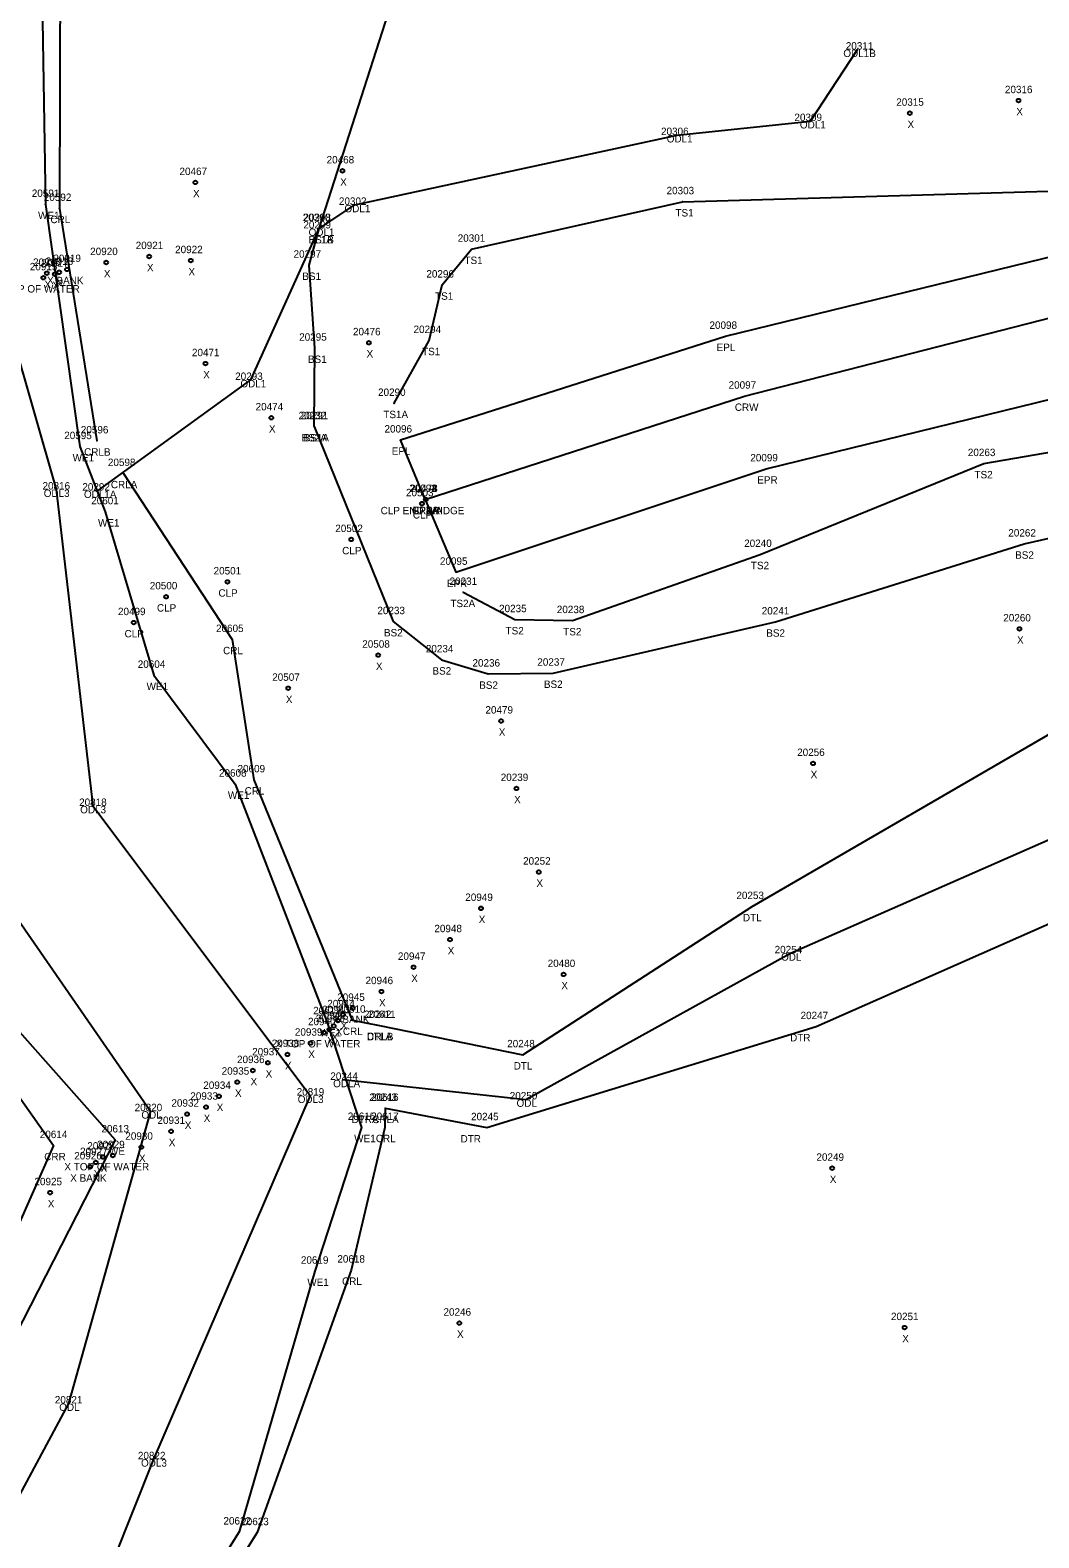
# Model space of a CAD drawing. Extents: x 1965722 to 1969964, y 1117078 to 1118461.
# Drawn here: x 1967825.7 to 1967961.8, y 1117755.3 to 1117958.8 of the extents above; entities that cross this region are included whole.
import ezdxf

# ---------------------------------------------------------------- set-up
doc = ezdxf.new("R2010")
doc.units = 0
for name, color, linetype in [('RD_DTM_BkLn1', 7, 'Continuous'), ('RD_DTM_BkLn2', 7, 'Continuous'), ('RD_EX_H2O', 7, 'Continuous'), ('RD_EX_H2O_txCode', 7, 'Continuous'), ('RD_EX_Road', 7, 'Continuous'), ('RD_EX_Road_txCode', 7, 'Continuous'), ('RD_SMD_Locator', 7, 'Continuous'), ('RD_SMD_Misc', 7, 'Continuous')]:
    doc.layers.add(name, color=color, linetype=linetype)

msp = doc.modelspace()

# ---------------------------------------------------------------- linework, layer by layer
at = {"layer": 'RD_DTM_BkLn1'}
for points in [[(1967864.65, 1117932.01), (1967874.44, 1117962.38), (1967900.7, 1118004.22), (1967938.17, 1118014.53)], [(1967878.98, 1117895.46), (1967922.07, 1117909.4), (1967968.89, 1117921.38), (1968013.49, 1117926.44), (1968059.29, 1117929.05), (1968105.63, 1117929.86), (1968159.12, 1117928.97), (1968212.65, 1117927.25), (1968318.5, 1117923.95), (1968422.42, 1117919.39), (1968529.36, 1117916.3)]]:
    msp.add_lwpolyline(points, dxfattribs=at)
at = {"layer": 'RD_DTM_BkLn2'}
for points in [[(1967874.77, 1117908.42), (1967879.51, 1117916.91), (1967881.27, 1117924.39), (1967885.24, 1117929.22), (1967913.7, 1117935.63), (1967966.11, 1117937.12), (1968012.39, 1117940.75), (1968059.42, 1117941.87), (1968105.44, 1117943.27), (1968158.32, 1117942.95), (1968212.48, 1117942.1), (1968371.25, 1117933.41), (1968422.85, 1117933.68), (1968531.49, 1117931.42)], [(1967864, 1117905.28), (1967864.09, 1117915.87), (1967863.33, 1117927.07), (1967864.65, 1117932.01)], [(1967884.1, 1117882.92), (1967891.06, 1117879.24), (1967898.84, 1117879.11), (1967924.17, 1117888.04), (1967954.33, 1117900.3), (1967970.81, 1117903.15), (1968012.93, 1117910.83), (1968059.62, 1117915.05), (1968105.25, 1117916.2), (1968157.57, 1117912.09), (1968210.74, 1117910.77), (1968320.32, 1117907.54), (1968423.18, 1117904.83), (1968528.99, 1117899.6)], [(1967864, 1117905.28), (1967874.64, 1117878.97), (1967881.18, 1117873.82), (1967887.49, 1117871.9), (1967896.22, 1117872.02), (1967926.22, 1117878.93), (1967959.79, 1117889.45), (1967973.08, 1117892.46), (1968014.67, 1117899.65), (1968058.49, 1117903.84)]]:
    msp.add_lwpolyline(points, dxfattribs=at)
at = {"layer": 'RD_EX_H2O'}
for points in [[(1967852.4, 1118390.04), (1967912.21, 1118383.64), (1967925.08, 1118336.82), (1967944.14, 1118294.4), (1967946.67, 1118243.15), (1967961.58, 1118191.28), (1967922.84, 1118148.62), (1967880.18, 1118117.11), (1967858.72, 1118073.64), (1967843.96, 1118030.69), (1967829.77, 1117984.65), (1967829.63, 1117934.73), (1967834.65, 1117903.36)], [(1967849.83, 1118135.18), (1967825.91, 1118086.77), (1967802.99, 1118041.98), (1967795.15, 1117992.28), (1967793.27, 1117935.35), (1967800.64, 1117889.8), (1967800.4, 1117872.52), (1967800.8, 1117854.99), (1967811.67, 1117837.73), (1967837.15, 1117809.04), (1967808.01, 1117752.12), (1967788.48, 1117706.78), (1967783.36, 1117689.17), (1967764.63, 1117648.93), (1967738.42, 1117613.44), (1967731.11, 1117607.31), (1967718.77, 1117573.47), (1967736.01, 1117517.29), (1967781.71, 1117484.69), (1967799.34, 1117478.73), (1967814.43, 1117469.18)], [(1967879.07, 1118118.61), (1967857.7, 1118074.04), (1967841.84, 1118031.93), (1967826.93, 1117984.9), (1967827.73, 1117935.27), (1967832.39, 1117902.59), (1967835.81, 1117893.8), (1967842.37, 1117871.73), (1967853.33, 1117857.05), (1967865.72, 1117824.99), (1967870.38, 1117810.73), (1967864.06, 1117791.33), (1967853.89, 1117756.14), (1967832.83, 1117722.61), (1967813.26, 1117679.41), (1967797.31, 1117630.26), (1967771.82, 1117595.7), (1967769.03, 1117583.97), (1967753.91, 1117565.22), (1967760.74, 1117542.39), (1967793.79, 1117511.28), (1967804.07, 1117502.92), (1967828.12, 1117499.18)], [(1967837.87, 1118086.59), (1967816.35, 1118042.52), (1967807.65, 1118000.54), (1967802.25, 1117964.95), (1967802.7, 1117929.05), (1967808.24, 1117891.66), (1967818.1, 1117847.27), (1967841.92, 1117812.91), (1967830.83, 1117773.47), (1967807.55, 1117730.13), (1967792.1, 1117688.21), (1967759.2, 1117626.42), (1967746.8, 1117597.58), (1967728.31, 1117575.82), (1967748.97, 1117519.79), (1967787.59, 1117491.86), (1967802.7, 1117484.72), (1967813.63, 1117479.24)], [(1967846.86, 1118079.71), (1967831.29, 1118034.88), (1967818.84, 1117997.76), (1967815.72, 1117964.67), (1967820.18, 1117928.06), (1967829.19, 1117896.79), (1967834.11, 1117854.1), (1967863.47, 1117815.02), (1967842.32, 1117765.95), (1967826.02, 1117725.1), (1967807.77, 1117682.35), (1967775.42, 1117611.81), (1967754.74, 1117587.12), (1967745.94, 1117565.65), (1967761.23, 1117525.28), (1967787.1, 1117502.15), (1967805.18, 1117494.11), (1967821.41, 1117490.36)], [(1967834.83, 1117896.65), (1967855.45, 1117911.58), (1967864.65, 1117932.01), (1967869.49, 1117935.2), (1967912.97, 1117944.62), (1967930.94, 1117946.51), (1967937.28, 1117956.15)], [(1967872.82, 1117824.49), (1967892.16, 1117820.53), (1967923.08, 1117840.53), (1967966.02, 1117865.44), (1967979.17, 1117870.44), (1968016.32, 1117890.41), (1968058.49, 1117903.84)], [(1967838.28, 1117898.96), (1967852.93, 1117876.56), (1967855.83, 1117857.63), (1967869.1, 1117825.19), (1967872.82, 1117824.49)], [(1967868.28, 1117817.14), (1967892.54, 1117814.5), (1967928.24, 1117834.22), (1967973.92, 1117854.29), (1967982.67, 1117861.15), (1968021.78, 1117883.3), (1968056.97, 1117897.44), (1968105.42, 1117898.77), (1968155.9, 1117899.84), (1968209.66, 1117898.76), (1968320.81, 1117895.57), (1968371.06, 1117895.25)], [(1967873.55, 1117813.3), (1967887.27, 1117810.69), (1967931.74, 1117824.33), (1967977.85, 1117844.69), (1967988.67, 1117850.69), (1968023.3, 1117871.08), (1968058.02, 1117883.74)], [(1967794.3, 1117875.45), (1967796.63, 1117853.43), (1967809.67, 1117835.4), (1967828.83, 1117808.28), (1967805.08, 1117754.56), (1967786.33, 1117708.04), (1967780.19, 1117689.35), (1967762.68, 1117651.19), (1967736.39, 1117616.3), (1967727.33, 1117611.21), (1967715.04, 1117573.35), (1967731.01, 1117514.73), (1967775.86, 1117468.11), (1967793.29, 1117458.88), (1967816.39, 1117454.18)], [(1967873.55, 1117813.3), (1967873.54, 1117810.73), (1967868.98, 1117791.48), (1967856.29, 1117756.05), (1967834.78, 1117721.72), (1967815.36, 1117678.52), (1967799.96, 1117628.39), (1967778.25, 1117587.63), (1967771.33, 1117582.11), (1967756.46, 1117564.6), (1967764.36, 1117543.85), (1967795.97, 1117517.33), (1967805.92, 1117513.21), (1967828.95, 1117503.56)]]:
    msp.add_lwpolyline(points, dxfattribs=at)
at = {"layer": 'RD_EX_Road'}
for points in [[(1967878.98, 1117895.46), (1967875.66, 1117903.48), (1967919.49, 1117917.47), (1967966.4, 1117928.95), (1968012.66, 1117935.42), (1968058.94, 1117938.37), (1968105.99, 1117939.39), (1968158.7, 1117938.56), (1968212.05, 1117937.21), (1968318.79, 1117933.28), (1968422.76, 1117929.93), (1968530.54, 1117925.7)], [(1967878.98, 1117895.46), (1967883.11, 1117885.63), (1967924.99, 1117899.59), (1967970.68, 1117910.78), (1968014.42, 1117916.56), (1968059.13, 1117919.49), (1968105.39, 1117920.31), (1968159.16, 1117919.37), (1968212.5, 1117917.97), (1968317.55, 1117914.44), (1968421.52, 1117910.75), (1968527.82, 1117906.41)]]:
    msp.add_lwpolyline(points, dxfattribs=at)
at = {"layer": 'RD_SMD_Locator'}
for centre, radius in [((1967937.28, 1117956.15), 0.001), ((1967959.04, 1117949.27), 0.25), ((1967944.36, 1117947.57), 0.25), ((1967930.94, 1117946.51), 0.001), ((1967912.97, 1117944.62), 0.001), ((1967867.81, 1117939.79), 0.25), ((1967847.96, 1117938.22), 0.25), ((1967827.73, 1117935.27), 0.001), ((1967913.7, 1117935.63), 0.001), ((1967829.63, 1117934.73), 0.001), ((1967869.49, 1117935.2), 0.001), ((1967864.65, 1117932.01), 0.001), ((1967864.65, 1117932.01), 0.001), ((1967864.65, 1117932.01), 0.001), ((1967885.24, 1117929.22), 0.001), ((1967835.93, 1117927.42), 0.25), ((1967841.74, 1117928.23), 0.25), ((1967847.35, 1117927.68), 0.25), ((1967827.45, 1117925.37), 0.25), ((1967827.92, 1117925.97), 0.25), ((1967829, 1117925.84), 0.25), ((1967829.59, 1117926.1), 0.25), ((1967830.64, 1117926.49), 0.25), ((1967863.33, 1117927.07), 0.001), ((1967881.27, 1117924.39), 0.001), ((1967879.51, 1117916.91), 0.001), ((1967919.49, 1117917.47), 0.001), ((1967864.09, 1117915.87), 0.001), ((1967871.37, 1117916.6), 0.25), ((1967849.33, 1117913.78), 0.25), ((1967855.45, 1117911.58), 0.001), ((1967922.07, 1117909.4), 0.001), ((1967874.77, 1117908.42), 0.001), ((1967858.21, 1117906.47), 0.25), ((1967864, 1117905.28), 0.001), ((1967864, 1117905.28), 0.001), ((1967834.65, 1117903.36), 0.001), ((1967875.66, 1117903.48), 0.001), ((1967832.39, 1117902.59), 0.001), ((1967838.28, 1117898.96), 0.001), ((1967924.99, 1117899.59), 0.001), ((1967954.33, 1117900.3), 0.001), ((1967829.19, 1117896.79), 0.001), ((1967834.83, 1117896.65), 0.001), ((1967878.54, 1117894.88), 0.25), ((1967879.05, 1117895.45), 0.25), ((1967878.98, 1117895.46), 0.001), ((1967878.98, 1117895.46), 0.001), ((1967878.98, 1117895.46), 0.001), ((1967835.81, 1117893.8), 0.001), ((1967869, 1117890.05), 0.25), ((1967959.79, 1117889.45), 0.001), ((1967924.17, 1117888.04), 0.001), ((1967852.29, 1117884.33), 0.25), ((1967883.11, 1117885.63), 0.001), ((1967844.01, 1117882.32), 0.25), ((1967884.1, 1117882.92), 0.001), ((1967839.64, 1117878.84), 0.25), ((1967874.64, 1117878.97), 0.001), ((1967891.06, 1117879.24), 0.001), ((1967898.84, 1117879.11), 0.001), ((1967926.22, 1117878.93), 0.001), ((1967852.93, 1117876.56), 0.001), ((1967959.15, 1117877.99), 0.25), ((1967872.64, 1117874.45), 0.25), ((1967881.18, 1117873.82), 0.001), ((1967842.37, 1117871.73), 0.001), ((1967860.49, 1117869.98), 0.25), ((1967887.49, 1117871.9), 0.001), ((1967896.22, 1117872.02), 0.001), ((1967889.22, 1117865.56), 0.25), ((1967931.3, 1117859.84), 0.25), ((1967853.33, 1117857.05), 0.001), ((1967855.83, 1117857.63), 0.001), ((1967891.28, 1117856.46), 0.25), ((1967834.11, 1117854.1), 0.001), ((1967894.3, 1117845.18), 0.25), ((1967886.5, 1117840.28), 0.25), ((1967923.08, 1117840.53), 0.001), ((1967882.32, 1117836.06), 0.25), ((1967928.24, 1117834.22), 0.001), ((1967877.41, 1117832.33), 0.25), ((1967897.65, 1117831.36), 0.25), ((1967873.06, 1117829.05), 0.25), ((1967867.2, 1117825.13), 0.25), ((1967867.88, 1117825.93), 0.25), ((1967869.21, 1117826.8), 0.25), ((1967865.32, 1117823.51), 0.25), ((1967865.72, 1117824.99), 0.001), ((1967866.04, 1117823.93), 0.25), ((1967866.64, 1117824.4), 0.25), ((1967869.1, 1117825.19), 0.001), ((1967872.82, 1117824.49), 0.001), ((1967872.82, 1117824.49), 0.001), ((1967931.74, 1117824.33), 0.001), ((1967863.5, 1117822.1), 0.25), ((1967857.75, 1117819.44), 0.25), ((1967860.38, 1117820.57), 0.25), ((1967892.16, 1117820.53), 0.001), ((1967855.73, 1117818.4), 0.25), ((1967853.62, 1117816.84), 0.25), ((1967868.28, 1117817.14), 0.001), ((1967849.4, 1117813.46), 0.25), ((1967851.15, 1117814.92), 0.25), ((1967863.47, 1117815.02), 0.001), ((1967873.55, 1117813.3), 0.001), ((1967873.55, 1117813.3), 0.001), ((1967892.54, 1117814.5), 0.001), ((1967841.92, 1117812.91), 0.001), ((1967846.84, 1117812.52), 0.25), ((1967844.69, 1117810.19), 0.25), ((1967870.38, 1117810.73), 0.001), ((1967873.54, 1117810.73), 0.001), ((1967887.27, 1117810.69), 0.001), ((1967828.83, 1117808.28), 0.001), ((1967836.83, 1117806.92), 0.25), ((1967837.15, 1117809.04), 0.001), ((1967840.67, 1117808.06), 0.25), ((1967833.76, 1117805.4), 0.25), ((1967834.53, 1117805.99), 0.25), ((1967835.5, 1117806.73), 0.25), ((1967933.88, 1117805.22), 0.25), ((1967828.37, 1117801.92), 0.25), ((1967864.06, 1117791.33), 0.001), ((1967868.98, 1117791.48), 0.001), ((1967883.58, 1117784.32), 0.25), ((1967943.66, 1117783.72), 0.25), ((1967830.83, 1117773.47), 0.001), ((1967842.32, 1117765.95), 0.001), ((1967853.89, 1117756.14), 0.001), ((1967856.29, 1117756.05), 0.001)]:
    msp.add_circle(centre, radius, dxfattribs=at)

# ---------------------------------------------------------------- texts
at = {"layer": 'RD_EX_H2O_txCode'}
for s, p in [('ODL1B', (1967935.39, 1117955.15)), ('20311', (1967935.72, 1117956.15)), ('20309', (1967928.79, 1117946.51)), ('20306', (1967910.79, 1117944.62)), ('ODL1', (1967929.53, 1117945.51)), ('ODL1', (1967911.56, 1117943.62)), ('20591', (1967825.89, 1117936.27)), ('20592', (1967827.51, 1117935.73)), ('20302', (1967867.33, 1117935.2)), ('ODL1', (1967868.08, 1117934.2)), ('WE1', (1967826.74, 1117933.27)), ('CRL', (1967828.4, 1117932.73)), ('20299', (1967862.53, 1117932.01)), ('ODL1', (1967863.24, 1117931.01)), ('20293', (1967853.33, 1117911.58)), ('ODL1', (1967854.04, 1117910.58)), ('20596', (1967832.51, 1117904.36)), ('20595', (1967830.27, 1117903.59)), ('WE1', (1967831.4, 1117900.59)), ('CRLB', (1967832.95, 1117901.36)), ('20598', (1967836.16, 1117899.96)), ('20816', (1967827.34, 1117896.79)), ('ODL3', (1967827.5, 1117895.79)), ('20292', (1967832.71, 1117896.65)), ('ODL1A', (1967832.93, 1117895.65)), ('CRLA', (1967836.56, 1117896.96)), ('20601', (1967833.91, 1117894.8)), ('WE1', (1967834.83, 1117891.8)), ('20605', (1967850.75, 1117877.56)), ('CRL', (1967851.7, 1117874.56)), ('20604', (1967840.19, 1117872.73)), ('WE1', (1967841.38, 1117869.73)), ('20608', (1967851.15, 1117858.05)), ('20609', (1967853.65, 1117858.63)), ('WE1', (1967852.35, 1117855.05)), ('CRL', (1967854.61, 1117855.63)), ('20818', (1967832.28, 1117854.1)), ('ODL3', (1967832.42, 1117853.1)), ('20253', (1967920.96, 1117841.53)), ('DTL', (1967921.84, 1117838.53)), ('20254', (1967926.12, 1117834.22)), ('ODL', (1967926.99, 1117833.22)), ('20612', (1967863.86, 1117825.99)), ('20610', (1967867.2, 1117826.19)), ('20242', (1967870.7, 1117825.49)), ('20611', (1967871.25, 1117825.49)), ('20247', (1967929.62, 1117825.33)), ('WE1', (1967864.74, 1117822.99)), ('CRL', (1967867.87, 1117823.19)), ('CRLB', (1967871.12, 1117822.49)), ('DTLA', (1967871.09, 1117822.49)), ('DTR', (1967928.21, 1117822.33)), ('20248', (1967890.04, 1117821.53)), ('DTL', (1967890.92, 1117818.53)), ('20244', (1967866.17, 1117817.14)), ('20819', (1967861.63, 1117815.02)), ('ODLA', (1967866.55, 1117816.14)), ('20243', (1967871.43, 1117814.3)), ('20616', (1967871.67, 1117814.3)), ('20250', (1967890.38, 1117814.5)), ('20820', (1967839.77, 1117812.91)), ('ODL3', (1967861.77, 1117814.02)), ('ODL', (1967891.3, 1117813.5)), ('ODL', (1967840.68, 1117811.91)), ('20615', (1967868.52, 1117811.73)), ('DTRA', (1967869.04, 1117811.3)), ('20617', (1967871.68, 1117811.73)), ('CRLA', (1967871.83, 1117811.3)), ('20245', (1967885.16, 1117811.69)), ('20614', (1967826.97, 1117809.28)), ('20613', (1967835.29, 1117810.04)), ('WE1', (1967869.39, 1117808.73)), ('CRL', (1967872.31, 1117808.73)), ('DTR', (1967883.74, 1117808.69)), ('CRR', (1967827.57, 1117806.28)), ('WE', (1967836.31, 1117807.04)), ('20619', (1967862.2, 1117792.33)), ('20618', (1967867.12, 1117792.48)), ('WE1', (1967863.07, 1117789.33)), ('CRL', (1967867.75, 1117789.48)), ('20821', (1967829, 1117773.47)), ('ODL', (1967829.59, 1117772.47)), ('20822', (1967840.21, 1117765.95)), ('ODL3', (1967840.63, 1117764.95)), ('20622', (1967851.75, 1117757.14)), ('20623', (1967854.15, 1117757.05))]:
    msp.add_text(s, height=1, dxfattribs=at).set_placement(p)
at = {"layer": 'RD_EX_Road_txCode'}
for s, p in [('20098', (1967917.33, 1117918.47)), ('EPL', (1967918.29, 1117915.47)), ('20096', (1967873.48, 1117904.48)), ('EPL', (1967874.46, 1117901.48)), ('20099', (1967922.84, 1117900.59)), ('20093', (1967876.82, 1117896.46)), ('20094', (1967876.82, 1117896.46)), ('EPR', (1967923.77, 1117897.59)), ('EPRA', (1967877.27, 1117893.46)), ('EPLA', (1967877.29, 1117893.46)), ('20095', (1967880.96, 1117886.63)), ('EPR', (1967881.89, 1117883.63))]:
    msp.add_text(s, height=1, dxfattribs=at).set_placement(p)
at = {"layer": 'RD_SMD_Misc'}
for s, p in [('20315', (1967942.53, 1117948.57)), ('20316', (1967957.19, 1117950.27)), ('X', (1967958.73, 1117947.27)), ('X', (1967944.05, 1117945.57)), ('20468', (1967865.67, 1117940.79)), ('20467', (1967845.82, 1117939.22)), ('X', (1967867.5, 1117937.79)), ('20303', (1967911.54, 1117936.63)), ('X', (1967847.65, 1117936.22)), ('20300', (1967862.45, 1117933.01)), ('20298', (1967862.53, 1117933.01)), ('TS1', (1967912.74, 1117933.63)), ('20301', (1967883.36, 1117930.22)), ('20920', (1967833.77, 1117928.42)), ('20921', (1967839.91, 1117929.23)), ('20922', (1967845.23, 1117928.68)), ('BS1B', (1967863.23, 1117930.01)), ('BL1A', (1967863.24, 1117930.01)), ('20915', (1967825.62, 1117926.37)), ('20916', (1967826.06, 1117926.97)), ('20917', (1967827.16, 1117926.84)), ('20918', (1967827.76, 1117927.1)), ('20919', (1967828.8, 1117927.49)), ('X', (1967841.43, 1117926.23)), ('20297', (1967861.21, 1117928.07)), ('TS1', (1967884.27, 1117927.22)), ('X BANK', (1967827.96, 1117924.49)), ('X', (1967829.28, 1117924.1)), ('X', (1967835.62, 1117925.42)), ('X', (1967847.03, 1117925.68)), ('BS1', (1967862.39, 1117925.07)), ('20296', (1967879.13, 1117925.39)), ('X TOP OF WATER', (1967820.91, 1117923.37)), ('X', (1967827.6, 1117923.97)), ('X', (1967828.68, 1117923.84)), ('TS1', (1967880.31, 1117922.39)), ('20295', (1967861.97, 1117916.87)), ('20476', (1967869.23, 1117917.6)), ('20294', (1967877.4, 1117917.91)), ('20471', (1967847.5, 1117914.78)), ('BS1', (1967863.15, 1117913.87)), ('X', (1967871.06, 1117914.6)), ('TS1', (1967878.55, 1117914.91)), ('X', (1967849.02, 1117911.78)), ('20097', (1967919.91, 1117910.4)), ('20290', (1967872.61, 1117909.42)), ('20474', (1967856.09, 1117907.47)), ('20232', (1967861.89, 1117906.28)), ('20291', (1967862.17, 1117906.28)), ('TS1A', (1967873.32, 1117906.42)), ('CRW', (1967920.75, 1117907.4)), ('X', (1967857.89, 1117904.47)), ('BS2A', (1967862.29, 1117903.28)), ('BS1A', (1967862.57, 1117903.28)), ('20263', (1967952.19, 1117901.3)), ('TS2', (1967953.09, 1117898.3)), ('20503', (1967876.38, 1117895.88)), ('20092', (1967876.82, 1117896.46)), ('20478', (1967876.94, 1117896.45)), ('CLP END BRIDGE', (1967872.96, 1117893.45)), ('CRWA', (1967877.18, 1117893.46)), ('CLP', (1967877.31, 1117892.88)), ('20502', (1967866.84, 1117891.05)), ('20262', (1967957.65, 1117890.45)), ('CLP', (1967867.77, 1117888.05)), ('20240', (1967922.01, 1117889.04)), ('BS2', (1967958.57, 1117887.45)), ('TS2', (1967922.92, 1117886.04)), ('20501', (1967850.42, 1117885.33)), ('20231', (1967882.26, 1117883.92)), ('20500', (1967841.81, 1117883.32)), ('CLP', (1967851.07, 1117882.33)), ('20499', (1967837.52, 1117879.84)), ('CLP', (1967842.78, 1117880.32)), ('20233', (1967872.52, 1117879.97)), ('TS2A', (1967882.37, 1117880.92)), ('20235', (1967888.94, 1117880.24)), ('20238', (1967896.73, 1117880.11)), ('20241', (1967924.38, 1117879.93)), ('TS2', (1967889.82, 1117877.24)), ('20260', (1967956.97, 1117878.99)), ('CLP', (1967838.41, 1117876.84)), ('20508', (1967870.48, 1117875.45)), ('BS2', (1967873.41, 1117876.97)), ('TS2', (1967897.6, 1117877.11)), ('BS2', (1967924.99, 1117876.93)), ('X', (1967958.83, 1117875.99)), ('20234', (1967879.06, 1117874.82)), ('X', (1967872.32, 1117872.45)), ('BS2', (1967879.95, 1117871.82)), ('20236', (1967885.35, 1117872.9)), ('20237', (1967894.1, 1117873.02)), ('20507', (1967858.33, 1117870.98)), ('BS2', (1967886.26, 1117869.9)), ('BS2', (1967894.99, 1117870.02)), ('X', (1967860.17, 1117867.98)), ('20479', (1967887.1, 1117866.56)), ('X', (1967888.9, 1117863.56)), ('20256', (1967929.16, 1117860.84)), ('20239', (1967889.16, 1117857.46)), ('X', (1967930.98, 1117857.84)), ('X', (1967890.97, 1117854.46)), ('20252', (1967892.18, 1117846.18)), ('X', (1967893.98, 1117843.18)), ('20949', (1967884.38, 1117841.28)), ('20948', (1967880.21, 1117837.06)), ('X', (1967886.19, 1117838.28)), ('20947', (1967875.29, 1117833.33)), ('X', (1967882.01, 1117834.06)), ('20480', (1967895.5, 1117832.36)), ('20946', (1967870.92, 1117830.05)), ('X', (1967877.09, 1117830.33)), ('X', (1967897.34, 1117829.36)), ('20944', (1967865.76, 1117826.93)), ('20945', (1967867.1, 1117827.8)), ('X', (1967872.74, 1117827.05)), ('20940', (1967863.16, 1117824.51)), ('20941', (1967864.21, 1117824.93)), ('20942', (1967864.52, 1117825.4)), ('20943', (1967865.08, 1117826.13)), ('X BANK', (1967866.54, 1117824.8)), ('20939', (1967861.39, 1117823.1)), ('X', (1967866.33, 1117822.4)), ('X', (1967866.89, 1117823.13)), ('X', (1967867.57, 1117823.93)), ('20937', (1967855.63, 1117820.44)), ('20938', (1967858.26, 1117821.57)), ('X TOP OF WATER', (1967858.79, 1117821.51)), ('X', (1967865.73, 1117821.93)), ('20936', (1967853.58, 1117819.4)), ('X', (1967860.06, 1117818.57)), ('X', (1967863.19, 1117820.1)), ('20935', (1967851.51, 1117817.84)), ('X', (1967855.41, 1117816.4)), ('X', (1967857.44, 1117817.44)), ('20933', (1967847.28, 1117814.46)), ('20934', (1967849.03, 1117815.92)), ('X', (1967853.31, 1117814.84)), ('20932', (1967844.73, 1117813.52)), ('X', (1967850.84, 1117812.92)), ('20931', (1967842.85, 1117811.19)), ('X', (1967846.53, 1117810.52)), ('X', (1967849.08, 1117811.46)), ('20930', (1967838.51, 1117809.06)), ('X', (1967844.37, 1117808.19)), ('20926', (1967831.62, 1117806.4)), ('20927', (1967832.41, 1117806.99)), ('20928', (1967833.38, 1117807.73)), ('20929', (1967834.71, 1117807.92)), ('X', (1967840.35, 1117806.06)), ('20249', (1967931.76, 1117806.22)), ('X TOP OF WATER', (1967830.29, 1117804.92)), ('X', (1967835.18, 1117804.73)), ('20925', (1967826.25, 1117802.92)), ('X BANK', (1967831.08, 1117803.4)), ('X', (1967834.21, 1117803.99)), ('X', (1967933.56, 1117803.22)), ('X', (1967828.05, 1117799.92)), ('20246', (1967881.44, 1117785.32)), ('20251', (1967941.82, 1117784.72)), ('X', (1967883.27, 1117782.32)), ('X', (1967943.34, 1117781.72))]:
    msp.add_text(s, height=1, dxfattribs=at).set_placement(p)

doc.saveas('drawing.dxf')
